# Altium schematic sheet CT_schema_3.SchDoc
size 300 x 177 mm
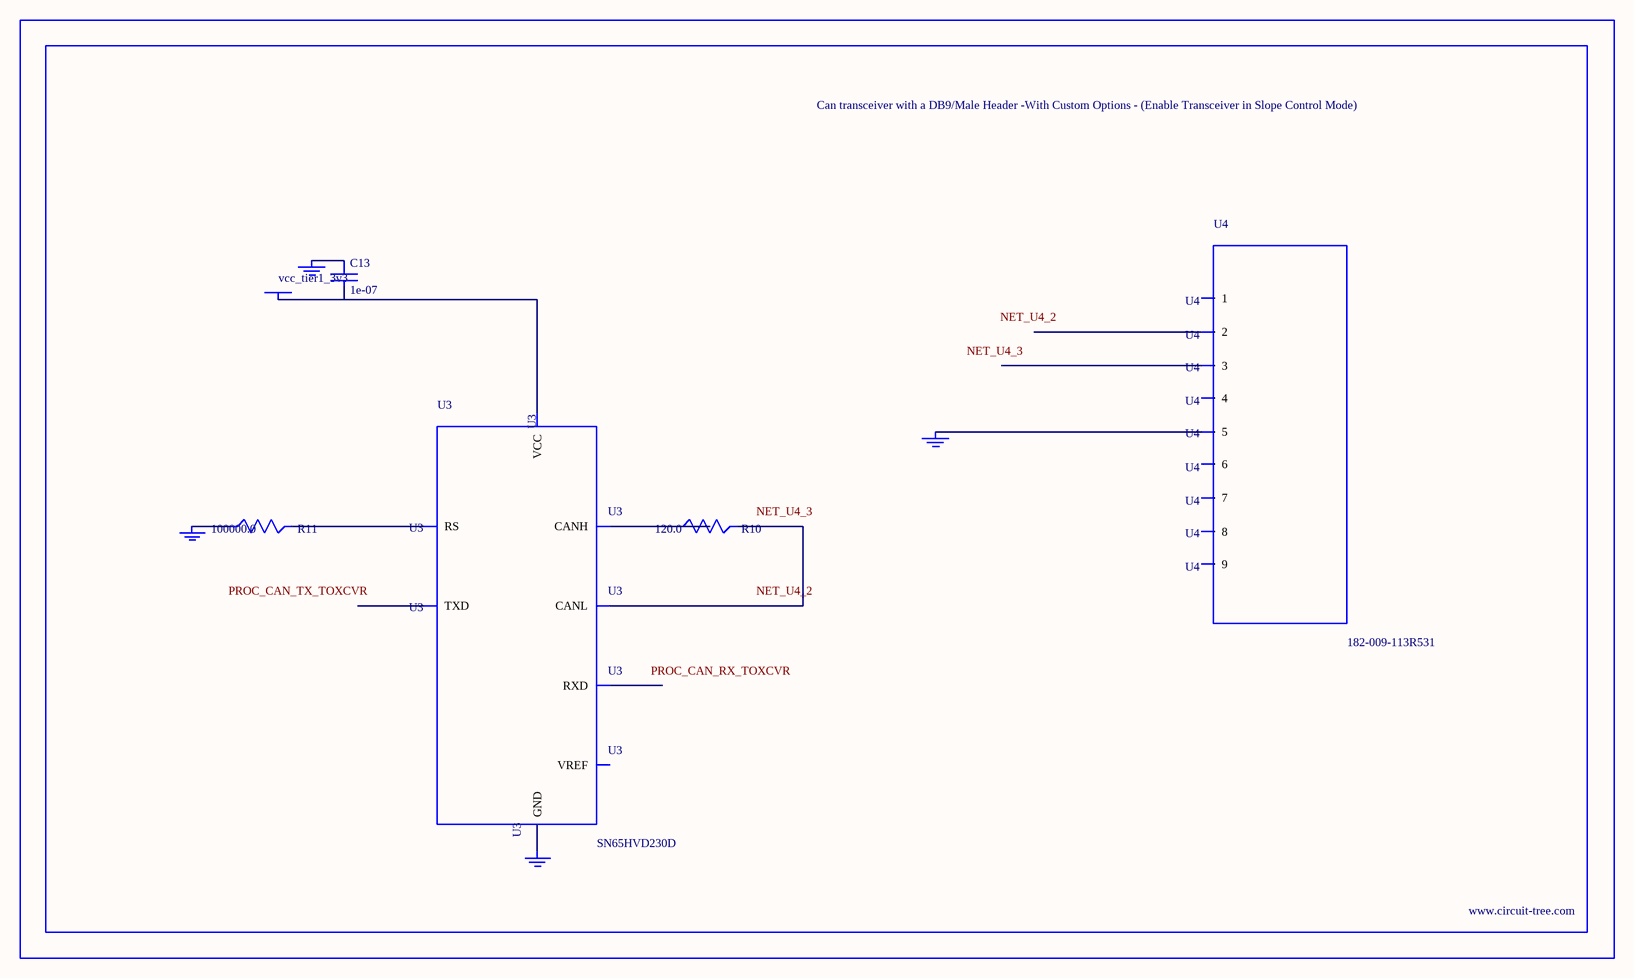
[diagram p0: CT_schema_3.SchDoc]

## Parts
BORDER2  (no value)
C13  1e-07  [C0402]
GND_INSTANCE_2_0  (no value)
GND_INSTANCE_2_1  (no value)
GND_INSTANCE_2_2  (no value)
GND_INSTANCE_2_3  (no value)
POWER_INSTANCE_2_0  vcc_tier1_3v3
R10  120.0  [R0603]
R11  100000.0  [R0603]
U3  SN65HVD230D  [SOIC-8]
U4  182-009-113R531  [182-009-MALE]

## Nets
NetC13_1: C13.1 GND_INSTANCE_2_0.0(GND)
NetC13_2: C13.2 POWER_INSTANCE_2_0.0(PWR) U3.3(VCC)
NetGND_INSTANCE_2_1_0: GND_INSTANCE_2_1.0(GND) R11.1
NetGND_INSTANCE_2_2_0: GND_INSTANCE_2_2.0(GND) U3.2(GND)
NetGND_INSTANCE_2_3_0: GND_INSTANCE_2_3.0(GND) U4.5
NetR10_1: R10.1 U3.7(CANH)
NetR10_2: R10.2 U3.6(CANL)
NetR11_2: R11.2 U3.8(RS)

Not connected (* = marked no-connect by the designer): U3 1(TXD) 4(RXD) 5(VREF); U4 1 2 3 4 6 7 8 9

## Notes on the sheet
- Labels drawn without touching a wire or pin: NET_U4_2, NET_U4_3, PROC_CAN_RX_TOXCVR, PROC_CAN_TX_TOXCVR

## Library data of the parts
BORDER2 = BORDER_PAGE2
C13 = C0402C104K3RACTU
GND_INSTANCE_2_0-GND_INSTANCE_2_3 = GND
POWER_INSTANCE_2_0 = PWR
R10 = RC0603JR-07120RL
R11 = RC0603JR-07100KL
